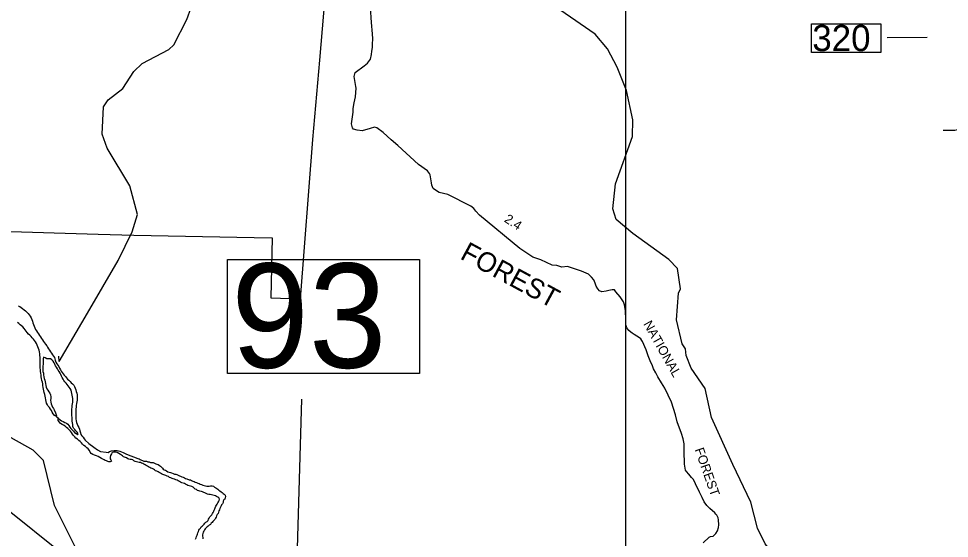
# Model space of a CAD drawing. Extents: x 1113032 to 1302912, y 664689 to 832535.
# Drawn here: x 1139525 to 1152008, y 758928 to 765901 of the extents above; entities that cross this region are included whole.
import ezdxf

# ---------------------------------------------------------------- set-up
doc = ezdxf.new("R2010")
doc.units = 0
for name, color, linetype in [('Exist Boundary Land Use Forest National US Forest Service', 7, 'Continuous'), ('Exist Hydrographic Creek Single Shore', 7, 'Continuous'), ('Exist Hydrographic Island Shore', 7, 'Continuous'), ('Exist Hydrographic River Shore', 7, 'Continuous'), ('Exist Road Non-System Type 51', 7, 'Continuous'), ('Exist Road Primary NC Structure Standard Bridge Number Label', 7, 'Continuous'), ('Exist Road Secondary Structure Standard Bridge Number Label', 7, 'Continuous'), ('Exist Road State Agency Type 20 National Forest', 7, 'Continuous'), ('Exist Road State Agency Type 41 Label', 7, 'Continuous'), ('Exist Road State Agency Type 41 Mileage Label', 7, 'Continuous'), ('Map Preparation Inset Cut Line', 7, 'Continuous')]:
    doc.layers.add(name, color=color, linetype=linetype)

msp = doc.modelspace()

# ---------------------------------------------------------------- linework, layer by layer
at = {"layer": 'Exist Boundary Land Use Forest National US Forest Service'}
for points in [[(1149151, 767363), (1149147, 767306), (1149106, 766801), (1147881, 766871), (1146455, 766944), (1145604, 766972), (1145497, 766975), (1144052, 766994), (1143524, 767596), (1143458, 767552), (1143356, 767483), (1143352, 767481), (1143455, 767371), (1143793, 767008), (1143705, 767031), (1143560, 765343), (1143468, 764280), (1143300, 762142)], [(1138479, 763072), (1138521, 763071), (1139266, 763048), (1140594, 763008), (1141070, 762998), (1142683, 762964), (1142926, 762959), (1142906, 762157), (1143300, 762142)]]:
    msp.add_lwpolyline(points, dxfattribs=at)
at = {"layer": 'Exist Hydrographic Creek Single Shore'}
for points in [[(1147761, 763019), (1147541, 763207), (1147496, 763349), (1147531, 763683), (1147758, 764319), (1147764, 764545), (1147677, 764938), (1147551, 765252), (1147425, 765497), (1147256, 765694), (1146594, 766154), (1145046, 767383), (1144982, 767486), (1144830, 767965), (1144652, 768454), (1144545, 769057), (1144396, 769362)], [(1140069, 761301), (1140449, 761951), (1140862, 762655), (1141048, 763042), (1141122, 763273), (1141016, 763659), (1140714, 764161), (1140645, 764353), (1140664, 764720), (1140725, 764811), (1140922, 764964), (1141070, 765191), (1141182, 765297), (1141538, 765487), (1141606, 765551), (1141783, 765889), (1141838, 766052), (1141854, 766328), (1141818, 766506), (1141685, 766791), (1141641, 767028), (1141615, 768111), (1141415, 768391), (1141419, 768516)], [(1150639, 756680), (1150613, 756742), (1150662, 757847), (1150589, 757944), (1150251, 758085), (1150080, 758223), (1149845, 758464), (1149539, 758854), (1149437, 759066), (1149347, 759413), (1149102, 759920), (1148820, 760552), (1148731, 760938), (1148547, 761211), (1148477, 761380), (1148471, 761472), (1148423, 761539), (1148348, 761858), (1148375, 762216), (1148402, 762274), (1148360, 762551), (1148246, 762671), (1147761, 763019)], [(1140950, 757478), (1140911, 757533), (1140840, 757598), (1140808, 757662), (1140809, 757673), (1140809, 757696), (1140791, 757711), (1140745, 757780), (1140713, 757882), (1140593, 758068), (1140486, 758389), (1140406, 758515), (1140400, 758581), (1140007, 759370), (1139857, 759973), (1139719, 760111), (1139424, 760278)]]:
    msp.add_lwpolyline(points, dxfattribs=at)
at = {"layer": 'Exist Hydrographic Island Shore'}
msp.add_lwpolyline([(1140055, 760542), (1140081, 760519), (1140101, 760506), (1140123, 760495), (1140145, 760484), (1140167, 760475), (1140187, 760462), (1140200, 760442), (1140213, 760421), (1140227, 760402), (1140244, 760384), (1140261, 760367), (1140277, 760349), (1140296, 760334), (1140314, 760317), (1140325, 760331), (1140311, 760351), (1140294, 760369), (1140278, 760388), (1140263, 760407), (1140254, 760429), (1140251, 760454), (1140247, 760478), (1140245, 760502), (1140243, 760526), (1140242, 760550), (1140241, 760575), (1140239, 760599), (1140238, 760617), (1140238, 760637), (1140239, 760663), (1140242, 760687), (1140245, 760710), (1140248, 760734), (1140251, 760757), (1140252, 760780), (1140251, 760803), (1140248, 760826), (1140243, 760849), (1140239, 760872), (1140234, 760895), (1140228, 760917), (1140217, 760937), (1140205, 760957), (1140192, 760976), (1140178, 760994), (1140163, 761011), (1140147, 761027), (1140134, 761046), (1140122, 761065), (1140111, 761085), (1140102, 761105), (1140091, 761125), (1140082, 761146), (1140070, 761165), (1140057, 761184), (1140045, 761204), (1140034, 761224), (1140020, 761243), (1140010, 761264), (1140000, 761285), (1139987, 761304), (1139971, 761323), (1139951, 761335), (1139927, 761337), (1139903, 761339), (1139882, 761352), (1139859, 761357), (1139853, 761337), (1139856, 761312), (1139855, 761288), (1139853, 761264), (1139851, 761240), (1139849, 761216), (1139849, 761192), (1139851, 761168), (1139857, 761145), (1139861, 761121), (1139865, 761097), (1139870, 761074), (1139876, 761051), (1139882, 761028), (1139887, 761004), (1139890, 760980), (1139894, 760956), (1139904, 760935), (1139918, 760915), (1139931, 760895), (1139944, 760875), (1139953, 760853), (1139958, 760829), (1139958, 760805), (1139954, 760781), (1139956, 760757), (1139962, 760734), (1139971, 760712), (1139982, 760690), (1139993, 760669), (1140000, 760652), (1140018, 760614)], dxfattribs=at)
at = {"layer": 'Exist Hydrographic River Shore'}
for points in [[(1139520, 762050), (1139540, 762037), (1139559, 762024), (1139579, 762010), (1139598, 761995), (1139616, 761980), (1139634, 761963), (1139652, 761947), (1139668, 761929), (1139682, 761910), (1139693, 761888), (1139702, 761866), (1139710, 761843), (1139718, 761821), (1139725, 761798), (1139734, 761775), (1139743, 761754), (1139754, 761732), (1139766, 761711), (1139779, 761691), (1139792, 761671), (1139805, 761651), (1139818, 761631), (1139832, 761611), (1139845, 761591)], [(1139808, 761406), (1139806, 761430), (1139802, 761453), (1139793, 761476), (1139785, 761499), (1139776, 761521), (1139766, 761542), (1139753, 761563), (1139739, 761582), (1139724, 761601), (1139708, 761619), (1139692, 761637), (1139675, 761653), (1139658, 761670), (1139642, 761688), (1139628, 761708), (1139614, 761727), (1139599, 761746), (1139583, 761764), (1139565, 761780), (1139546, 761795), (1139528, 761810), (1139509, 761825)], [(1139845, 761591), (1139859, 761571), (1139873, 761552), (1139888, 761533), (1139902, 761513), (1139915, 761493), (1139928, 761473), (1139941, 761453), (1139953, 761432), (1139965, 761411), (1139978, 761391), (1139993, 761372), (1140005, 761353), (1140015, 761317), (1140024, 761290), (1140038, 761271), (1140052, 761252), (1140065, 761233), (1140075, 761212), (1140085, 761191), (1140097, 761172), (1140109, 761152), (1140122, 761134), (1140138, 761117), (1140152, 761099), (1140166, 761081), (1140182, 761065), (1140199, 761049), (1140215, 761033), (1140232, 761017), (1140249, 761001), (1140265, 760984), (1140276, 760964), (1140284, 760942), (1140292, 760920), (1140299, 760898), (1140306, 760876), (1140309, 760853), (1140311, 760830), (1140312, 760806), (1140310, 760783), (1140306, 760760), (1140301, 760737), (1140299, 760713), (1140297, 760690), (1140295, 760666), (1140293, 760641), (1140293, 760621), (1140293, 760603), (1140293, 760579), (1140294, 760554), (1140295, 760530), (1140297, 760506), (1140302, 760482), (1140310, 760459), (1140321, 760438), (1140331, 760415), (1140340, 760393), (1140348, 760370), (1140354, 760346), (1140361, 760323), (1140375, 760303), (1140390, 760284), (1140404, 760264), (1140420, 760246), (1140469, 760201), (1140532, 760152), (1140583, 760114), (1140623, 760093), (1140700, 760083), (1140727, 760082), (1140746, 760092), (1140773, 760101), (1140806, 760106), (1140847, 760106), (1140883, 760100), (1140929, 760081), (1140973, 760059), (1141124, 760000), (1141140, 759994), (1141157, 759987), (1141172, 759978), (1141189, 759971), (1141207, 759966), (1141224, 759964), (1141242, 759962), (1141259, 759955), (1141278, 759954), (1141295, 759948), (1141314, 759948), (1141331, 759944), (1141347, 759937), (1141364, 759929), (1141380, 759922), (1141397, 759917), (1141413, 759907), (1141428, 759897), (1141441, 759885), (1141453, 759872), (1141463, 759857)], [(1140035, 760575), (1140018, 760569), (1140000, 760582), (1139987, 760599), (1139974, 760620), (1139965, 760642), (1139953, 760662), (1139938, 760682), (1139924, 760701), (1139911, 760721), (1139901, 760743), (1139894, 760766), (1139889, 760789), (1139886, 760813), (1139882, 760837), (1139877, 760860), (1139870, 760883), (1139864, 760907), (1139859, 760930), (1139855, 760954), (1139852, 760978), (1139849, 761001), (1139845, 761025), (1139838, 761048), (1139833, 761072), (1139829, 761095), (1139826, 761119), (1139822, 761143), (1139819, 761167), (1139817, 761190), (1139816, 761214), (1139815, 761238), (1139815, 761262), (1139815, 761286), (1139816, 761310), (1139815, 761334), (1139813, 761358), (1139811, 761382), (1139808, 761406)], [(1140069, 761301), (1140065, 761373)], [(1140018, 760614), (1140024, 760597), (1140035, 760575)], [(1140055, 760542), (1140040, 760553), (1140035, 760575)], [(1141105, 759956), (1141088, 759961), (1141072, 759969), (1141058, 759981), (1141041, 759985), (1141023, 759987), (1141005, 759992), (1140988, 759997), (1140972, 760008), (1140933, 760023), (1140919, 760034), (1140890, 760055), (1140868, 760067), (1140847, 760079), (1140824, 760086), (1140800, 760086), (1140778, 760079), (1140769, 760063), (1140759, 760041), (1140754, 760018), (1140753, 759996), (1140762, 759981), (1140770, 759964), (1140755, 759953), (1140737, 759954), (1140720, 759960), (1140704, 759967), (1140687, 759975), (1140671, 759983), (1140655, 759991), (1140639, 760000), (1140614, 760012), (1140593, 760025), (1140569, 760035), (1140545, 760043), (1140521, 760052), (1140499, 760065), (1140486, 760086), (1140475, 760108), (1140460, 760128), (1140441, 760144), (1140421, 760159), (1140401, 760174), (1140383, 760191), (1140368, 760209), (1140351, 760226), (1140332, 760242), (1140313, 760257), (1140295, 760272), (1140278, 760289), (1140261, 760307), (1140247, 760327), (1140235, 760348), (1140221, 760367), (1140205, 760386), (1140187, 760402), (1140168, 760417), (1140149, 760432), (1140129, 760445), (1140108, 760457), (1140088, 760471), (1140072, 760489), (1140058, 760509), (1140055, 760542)], [(1141924, 758986), (1141930, 759003), (1141936, 759020), (1141943, 759037), (1141952, 759052), (1141963, 759066), (1141974, 759081), (1141986, 759094), (1141999, 759107), (1142012, 759120), (1142024, 759133), (1142038, 759145), (1142053, 759155), (1142066, 759169), (1142073, 759186), (1142082, 759201), (1142092, 759216), (1142103, 759231), (1142115, 759244), (1142124, 759260), (1142133, 759275), (1142142, 759291), (1142150, 759307), (1142157, 759324), (1142163, 759340), (1142171, 759358), (1142180, 759373), (1142189, 759389), (1142197, 759405), (1142208, 759419), (1142217, 759435), (1142219, 759453), (1142210, 759470), (1142195, 759479), (1142179, 759488), (1142164, 759497), (1142146, 759502), (1142129, 759507), (1142111, 759511), (1142094, 759516), (1142076, 759518), (1142059, 759523), (1142042, 759531), (1142025, 759537), (1142009, 759545), (1141993, 759552), (1141976, 759557), (1141958, 759561), (1141941, 759566), (1141924, 759572), (1141909, 759582), (1141893, 759590), (1141879, 759601), (1141866, 759614), (1141849, 759623), (1141831, 759627), (1141814, 759634), (1141797, 759639), (1141781, 759648), (1141765, 759656), (1141749, 759663), (1141732, 759670), (1141714, 759674), (1141698, 759682), (1141683, 759691), (1141667, 759701), (1141651, 759708), (1141634, 759714), (1141617, 759721), (1141600, 759727), (1141583, 759732), (1141566, 759739), (1141550, 759747), (1141535, 759756), (1141519, 759764), (1141502, 759770), (1141485, 759776), (1141459, 759787), (1141442, 759794), (1141427, 759804), (1141411, 759813), (1141395, 759821), (1141379, 759828), (1141363, 759836), (1141347, 759846), (1141333, 759856), (1141317, 759864), (1141300, 759870), (1141284, 759879), (1141269, 759889), (1141253, 759895), (1141237, 759905), (1141221, 759913), (1141207, 759924), (1141192, 759934), (1141175, 759939), (1141158, 759944), (1141140, 759948), (1141123, 759952), (1141105, 759956)], [(1141463, 759857), (1141479, 759849), (1141495, 759841), (1141511, 759832), (1141527, 759823), (1141543, 759816), (1141561, 759811), (1141578, 759807), (1141596, 759799), (1141614, 759791), (1141632, 759788), (1141649, 759784), (1141666, 759777), (1141682, 759769), (1141698, 759761), (1141715, 759754), (1141732, 759748), (1141748, 759741), (1141764, 759732), (1141781, 759726), (1141811, 759715), (1141829, 759712), (1141846, 759705), (1141862, 759697), (1141878, 759689), (1141894, 759682), (1141911, 759676), (1141928, 759669), (1141945, 759663), (1141962, 759657), (1141978, 759649), (1141995, 759644), (1142013, 759639), (1142030, 759633), (1142048, 759630), (1142065, 759628), (1142083, 759630), (1142101, 759631), (1142119, 759631), (1142138, 759627), (1142153, 759617), (1142169, 759607), (1142184, 759599), (1142199, 759589), (1142212, 759576), (1142225, 759564), (1142240, 759553), (1142254, 759543), (1142268, 759532), (1142282, 759520), (1142294, 759507), (1142300, 759490), (1142297, 759472), (1142289, 759456), (1142276, 759444), (1142269, 759427), (1142267, 759409), (1142259, 759393), (1142248, 759379), (1142240, 759363), (1142233, 759346), (1142225, 759330), (1142218, 759313), (1142211, 759296), (1142206, 759279), (1142200, 759262), (1142190, 759247), (1142179, 759231), (1142173, 759214), (1142166, 759197), (1142156, 759182), (1142144, 759168), (1142132, 759156), (1142120, 759142), (1142107, 759130), (1142097, 759115), (1142082, 759104), (1142069, 759092), (1142055, 759081), (1142041, 759069), (1142029, 759056), (1142018, 759042), (1142009, 759026), (1142002, 759010), (1141996, 758993), (1141992, 758975), (1141992, 758957), (1141996, 758940), (1141997, 758922)], [(1141899, 758919), (1141908, 758934), (1141912, 758952), (1141918, 758969), (1141924, 758986)]]:
    msp.add_lwpolyline(points, dxfattribs=at)
at = {"layer": 'Exist Road Non-System Type 51'}
msp.add_lwpolyline([(1152591, 764472), (1152550, 764489), (1152530, 764494), (1152510, 764497), (1152446, 764492), (1152388, 764484), (1152238, 764444), (1152135, 764413), (1152081, 764402), (1152051, 764399), (1151923, 764399)], dxfattribs=at)
at = {"layer": 'Exist Road Primary NC Structure Standard Bridge Number Label'}
msp.add_line((1143226, 757481), (1143323, 760794), dxfattribs=at)
msp.add_lwpolyline([(1142327, 762668), (1144904, 762668), (1144904, 761138), (1142327, 761138)], close=True, dxfattribs=at)
at = {"layer": 'Exist Road Secondary Structure Standard Bridge Number Label'}
for p, q in [((1151711, 765650), (1151173, 765642)), ((1141184, 757866), (1138414, 760075))]:
    msp.add_line(p, q, dxfattribs=at)
msp.add_lwpolyline([(1150158, 765830), (1151087, 765830), (1151087, 765446), (1150158, 765446)], close=True, dxfattribs=at)
at = {"layer": 'Exist Road State Agency Type 20 National Forest'}
for points in [[(1145284, 763542), (1145167, 763567), (1145116, 763599), (1145085, 763622), (1145068, 763665), (1145063, 763700), (1145046, 763806), (1145034, 763823), (1145008, 763861), (1144888, 763943), (1144611, 764197), (1144520, 764277), (1144466, 764322), (1144413, 764373), (1144330, 764436), (1144298, 764443), (1144238, 764428), (1144134, 764398), (1144068, 764405), (1144018, 764420), (1144003, 764435), (1143992, 764488), (1143999, 764551), (1144010, 764646), (1144014, 764694), (1144027, 764771), (1144042, 764852), (1144054, 764967), (1144049, 764991), (1144027, 765125), (1144041, 765179), (1144161, 765268), (1144203, 765303), (1144243, 765357), (1144259, 765419), (1144262, 765463), (1144272, 765513), (1144271, 765557), (1144278, 765629), (1144273, 765699), (1144259, 765848), (1144246, 766056)], [(1146246, 762816), (1145707, 763263), (1145656, 763318), (1145629, 763353), (1145591, 763387), (1145284, 763542)], [(1148704, 758867), (1148787, 758945), (1148804, 758954), (1148839, 758958), (1148876, 758995), (1148899, 759031), (1148911, 759072), (1148915, 759110), (1148913, 759179), (1148906, 759203), (1148891, 759238), (1148876, 759251), (1148863, 759271), (1148797, 759330), (1148757, 759367), (1148721, 759417), (1148693, 759478), (1148658, 759550), (1148603, 759659), (1148575, 759718), (1148551, 759746), (1148513, 759788), (1148482, 759827), (1148470, 759843), (1148456, 759922), (1148453, 760097), (1148451, 760198), (1148436, 760264), (1148416, 760336), (1148359, 760491), (1148335, 760586), (1148280, 760756), (1148238, 760850), (1148190, 760942), (1148147, 761015), (1148099, 761095), (1148072, 761150), (1148042, 761201), (1148028, 761242), (1147997, 761312), (1147969, 761377), (1147941, 761459), (1147894, 761571), (1147885, 761584), (1147870, 761603), (1147852, 761617), (1147780, 761662), (1147752, 761683), (1147734, 761694), (1147708, 761716), (1147684, 761752), (1147669, 761793), (1147668, 761816), (1147669, 761862), (1147665, 761986), (1147652, 762062), (1147638, 762101), (1147619, 762129), (1147592, 762167), (1147535, 762236), (1147515, 762261), (1147488, 762261), (1147442, 762254), (1147405, 762244), (1147347, 762236), (1147318, 762250), (1147292, 762277), (1147271, 762310), (1147257, 762350), (1147238, 762395), (1147210, 762434), (1147169, 762472), (1147073, 762515), (1146888, 762576), (1146810, 762568), (1146743, 762588), (1146683, 762592), (1146527, 762664), (1146420, 762702), (1146246, 762816)]]:
    msp.add_lwpolyline(points, dxfattribs=at)
at = {"layer": 'Map Preparation Inset Cut Line'}
msp.add_lwpolyline([(1147669, 777587), (1223352, 777587), (1223352, 748878), (1147669, 748878)], close=True, dxfattribs=at)

# ---------------------------------------------------------------- texts
at = {"layer": 'Exist Road Primary NC Structure Standard Bridge Number Label'}
msp.add_text('93', height=1400, dxfattribs=at).set_placement((1142377, 761217))
at = {"layer": 'Exist Road Secondary Structure Standard Bridge Number Label'}
msp.add_text('320', height=350, dxfattribs=at).set_placement((1150170, 765466))
at = {"layer": 'Exist Road State Agency Type 41 Label'}
for s, height, rotation, p in [('FOREST', 262.5, 331.581, (1145433, 762686)), ('NATIONAL', 125, 299.3994, (1147900, 761806)), ('FOREST', 125, 289.3074, (1148591, 760120))]:
    msp.add_text(s, height=height, rotation=rotation, dxfattribs=at).set_placement(p)
at = {"layer": 'Exist Road State Agency Type 41 Mileage Label'}
msp.add_text('2.4', height=125, rotation=326.8905, dxfattribs=at).set_placement((1146028, 763183))

doc.saveas('drawing.dxf')
